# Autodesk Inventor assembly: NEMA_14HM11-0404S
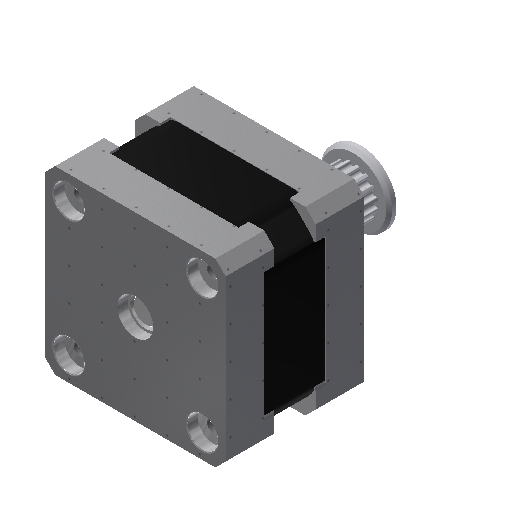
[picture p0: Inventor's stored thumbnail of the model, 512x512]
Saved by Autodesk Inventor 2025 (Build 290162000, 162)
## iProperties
Created: 2019-11
Part Number: NEMA_14HM11-0404S
Material: Générique
Document SubType Name: Assembly
Designer: thoma
Author: thoma
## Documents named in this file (4)
- C:\Users\R5800u\Desktop\nema14\NEMA_14HM11-0404S.iam
- C:\Users\R5800u\Desktop\nema14\NEMA_14HM11-0404S_BODY.ipt
- C:\Users\R5800u\Desktop\nema14\NEMA_14HM11-0404S_SHAFT.ipt
- C:\Users\R5800u\Desktop\nema14\GT2 16 Teeth Free Pulley.ipt
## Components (3 placed, 3 different names)
1. NEMA_14HM11-0404S:1 — Affleurement:2, Placage:2, Placage:3, Affleurement:3, Rotazionale:1
2. NEMA_14HM11-0404S_SHAFT:1 — Affleurement:3
3. GT2 16 Teeth Free Pulley:1 — Rotazionale:1
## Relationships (5: Flush 2, Mate 2, RevoluteJoint 1)
- Affleurement:2 [Flush]: NEMA_14HM11-0404S:1
- Placage:2 [Mate]: NEMA_14HM11-0404S:1
- Placage:3 [Mate]: NEMA_14HM11-0404S:1
- Affleurement:3 [Flush]: NEMA_14HM11-0404S:1 ↔ NEMA_14HM11-0404S_SHAFT:1
- Rotazionale:1 [RevoluteJoint]: NEMA_14HM11-0404S:1 ↔ GT2 16 Teeth Free Pulley:1
